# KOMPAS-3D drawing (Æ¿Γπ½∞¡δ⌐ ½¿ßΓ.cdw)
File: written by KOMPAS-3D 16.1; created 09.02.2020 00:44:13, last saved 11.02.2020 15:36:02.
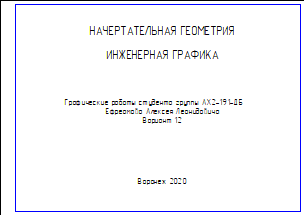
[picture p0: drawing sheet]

Sheet 1: A3, landscape

Title block, sheet 1: scale: 1:1; sheets: 1; sheet format: A3

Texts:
  Пользователь Windows
  НАЧЕРТАТЕЛЬНАЯ ГЕОМЕТРИЯ
  ИНЖЕНЕРНАЯ ГРАФИКА
  Графические работы студента группы АХ2-191-ДБ
  Ефреамова Алексея Леонидовича
  Вариант 12
  Воронеж 2020
  Без основной надписи.
Dimensions and other numbers on the sheet: 1:1; 1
